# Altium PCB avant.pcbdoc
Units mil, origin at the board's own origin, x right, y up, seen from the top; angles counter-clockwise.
Board outline 360 x 525 mil, 2 copper layers (Top Layer, Bottom Layer), stack 62.2 mil thick; 5 components, 6 nets, 26 pads, 7 vias.
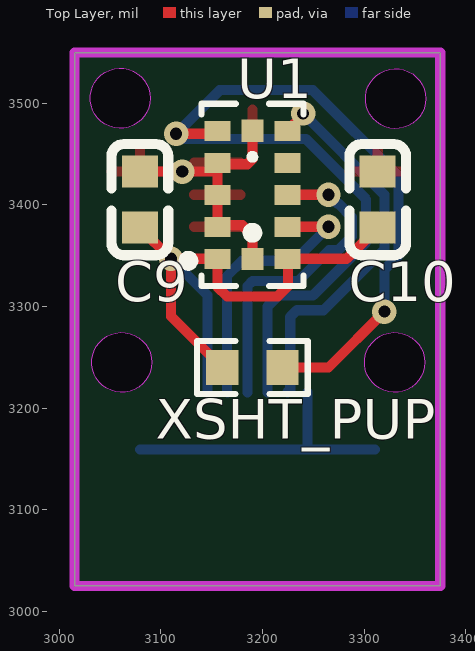
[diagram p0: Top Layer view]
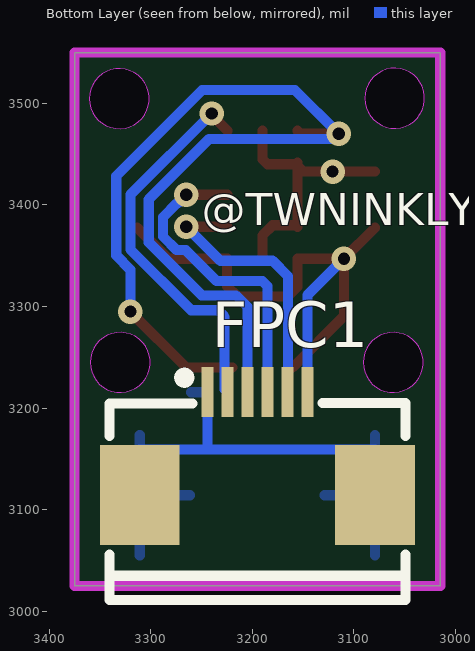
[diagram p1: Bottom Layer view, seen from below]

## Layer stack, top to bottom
Top Solder Mask Layer: solder mask 0.4, Dk 3.3
Top Layer: signal copper 1.4
Dielectric1: surface 59.4, FR4, Dk 4.5
Bottom Layer: signal copper 1.4
Bottom Solder Mask Layer: solder mask 0.4, Dk 3.3

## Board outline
3015,3550 3015,3025 3375,3025 3375,3550
cut-out: 3089.5,3505 3089.1,3500.3 3088,3495.6 3086.1,3491.3 3083.6,3487.3 3080.5,3483.7 3076.8,3480.7 3072.7,3478.3 3068.2,3476.6 3063.6,3475.7 3058.8,3475.5 3054.1,3476.1 3049.5,3477.4 3045.2,3479.4 3041.3,3482.1 3037.9,3485.4 3035,3489.2 3032.8,3493.4 3031.3,3497.9 3030.6,3502.6 3030.6,3507.4 3031.3,3512.1 3032.8,3516.6 3035,3520.8 3037.9,3524.6 3041.3,3527.9 3045.2,3530.6 3049.5,3532.6 3054.1,3533.9 3058.8,3534.5 3063.6,3534.3 3068.2,3533.4 3072.7,3531.7 3076.8,3529.3 3080.5,3526.3 3083.6,3522.7 3086.1,3518.7 3088,3514.4 3089.1,3509.7
cut-out: 3359.5,3245 3359.1,3240.3 3358,3235.6 3356.1,3231.3 3353.6,3227.3 3350.5,3223.7 3346.8,3220.7 3342.7,3218.3 3338.2,3216.6 3333.6,3215.7 3328.8,3215.5 3324.1,3216.1 3319.5,3217.4 3315.2,3219.4 3311.3,3222.1 3307.9,3225.4 3305,3229.2 3302.8,3233.4 3301.3,3237.9 3300.6,3242.6 3300.6,3247.4 3301.3,3252.1 3302.8,3256.6 3305,3260.8 3307.9,3264.6 3311.3,3267.9 3315.2,3270.6 3319.5,3272.6 3324.1,3273.9 3328.8,3274.5 3333.6,3274.3 3338.2,3273.4 3342.7,3271.7 3346.8,3269.3 3350.5,3266.3 3353.6,3262.7 3356.1,3258.7 3358,3254.4 3359.1,3249.7
cut-out: 3090.9,3245 3090.5,3240.3 3089.4,3235.6 3087.5,3231.3 3085,3227.3 3081.8,3223.7 3078.1,3220.7 3074,3218.3 3069.6,3216.6 3064.9,3215.7 3060.2,3215.5 3055.5,3216.1 3050.9,3217.4 3046.6,3219.4 3042.7,3222.1 3039.3,3225.4 3036.4,3229.2 3034.2,3233.4 3032.7,3237.9 3031.9,3242.6 3031.9,3247.4 3032.7,3252.1 3034.2,3256.6 3036.4,3260.8 3039.3,3264.6 3042.7,3267.9 3046.6,3270.6 3050.9,3272.6 3055.5,3273.9 3060.2,3274.5 3064.9,3274.3 3069.6,3273.4 3074,3271.7 3078.1,3269.3 3081.8,3266.3 3085,3262.7 3087.5,3258.7 3089.4,3254.4 3090.5,3249.7
cut-out: 3360.5,3504.6 3360.1,3499.9 3359,3495.3 3357.1,3490.9 3354.6,3486.9 3351.5,3483.3 3347.8,3480.3 3343.7,3477.9 3339.2,3476.3 3334.6,3475.3 3329.8,3475.1 3325.1,3475.7 3320.5,3477 3316.2,3479 3312.3,3481.7 3308.9,3485 3306,3488.8 3303.8,3493 3302.3,3497.5 3301.6,3502.2 3301.6,3507 3302.3,3511.7 3303.8,3516.2 3306,3520.4 3308.9,3524.2 3312.3,3527.5 3316.2,3530.2 3320.5,3532.2 3325.1,3533.5 3329.8,3534.1 3334.6,3533.9 3339.2,3533 3343.7,3531.3 3347.8,3528.9 3351.5,3525.9 3354.6,3522.4 3357.1,3518.3 3359,3514 3360.1,3509.4

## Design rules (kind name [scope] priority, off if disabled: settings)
BoardOutlineClearance copperThickness1oz [All] p0: genericclearance=10 ignorepadtopadclearanceinfootprint=FALSE except(0: Arc-SplitContinuation Track-SplitContinuation SMDPad-SplitContinuation THPad-SplitContinuation Via-SplitContinuation Fill-SplitContinuation Poly-SplitContinuation Region-SplitContinuation Text-SplitContinuation)
BoardOutlineClearance copperThickness2oz [All] p0: genericclearance=10 ignorepadtopadclearanceinfootprint=FALSE except(0: Arc-SplitContinuation Track-SplitContinuation SMDPad-SplitContinuation THPad-SplitContinuation Via-SplitContinuation Fill-SplitContinuation Poly-SplitContinuation Region-SplitContinuation Text-SplitContinuation)
BoardOutlineClearance Plane_innerPlane [All] p0: genericclearance=10 ignorepadtopadclearanceinfootprint=FALSE except(0: Arc-SplitContinuation Track-SplitContinuation SMDPad-SplitContinuation THPad-SplitContinuation Via-SplitContinuation Fill-SplitContinuation Poly-SplitContinuation Region-SplitContinuation Text-SplitContinuation)
BoardOutlineClearance Copper_copperRegion [All] p0: genericclearance=10 ignorepadtopadclearanceinfootprint=FALSE except(0: Arc-SplitContinuation Track-SplitContinuation SMDPad-SplitContinuation THPad-SplitContinuation Via-SplitContinuation Fill-SplitContinuation Poly-SplitContinuation Region-SplitContinuation Text-SplitContinuation)
BoardOutlineClearance otherClearance [All] p0: genericclearance=10 ignorepadtopadclearanceinfootprint=FALSE except(0: Arc-SplitContinuation Track-SplitContinuation SMDPad-SplitContinuation THPad-SplitContinuation Via-SplitContinuation Fill-SplitContinuation Poly-SplitContinuation Region-SplitContinuation Text-SplitContinuation)
Clearance copperThickness1oz [All] p1: gap=7 ignorepadtopadclearanceinfootprint=FALSE
Clearance copperThickness2oz [All] p1: gap=7 ignorepadtopadclearanceinfootprint=FALSE
Clearance Plane_innerPlane [All] p1: gap=7 ignorepadtopadclearanceinfootprint=FALSE
Clearance Copper_copperRegion [All] p1: gap=7 ignorepadtopadclearanceinfootprint=FALSE
Clearance otherClearance [All] p1: gap=7 ignorepadtopadclearanceinfootprint=FALSE
DiffPairsRouting differentialPair [All] p1: maxuncoupledlength=10 minlimit=6 maxlimit=Infinity mostfreqgap=6 toplayer_minwidth=5 toplayer_prefwidth=10 toplayer_maxwidth=100 bottomlayer_minwidth=5 bottomlayer_prefwidth=10 bottomlayer_maxwidth=100
PasteMaskExpansion pasteMaskExpansion [All] p1: expansion=0
PlaneConnect innerPlane [All] p1: planeconnectstyle=Relief reliefexpansion=20 reliefentries=4 reliefconductorwidth=10 reliefairgap=10
PolygonConnect copperRegion [All] p1: connectstyle=Relief reliefentries=4 reliefconductorwidth=10 polygonreliefangle="90 Angle" airgapwidth=10
RoutingVias viaSize [All] p1: viastyle="Through Hole" holewidth=12.0078 minholewidth=11.811 maxholewidth=248.0314 width=12.0078 minwidth=11.811 maxwidth=248.0314
SolderMaskExpansion solderMaskExpansion [IsVia] p1: useseparateexpansions=TRUE expansion=-1000 expansionbottom=-1000
SolderMaskExpansion solderMaskExpansion [All] p2: useseparateexpansions=TRUE expansion=2 expansionbottom=2
Width copperThickness1oz [All] p1: maxlimit=100 minlimit=5 preferedwidth=10
Width copperThickness2oz [All] p1: maxlimit=100 minlimit=8 preferedwidth=10

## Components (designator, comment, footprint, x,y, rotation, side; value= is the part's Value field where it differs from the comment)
C9 "100nF" C0603 3079.3,3405.2 r90 top
C10 "4.7uF" C0603 3313.4,3405.2 r90 top
FPC1 "FPC-05F-6PH20" FPC-SMD_6P-P0.50_XUNPU_FPC-05F-6PH20 3195,3165 r180 bottom
U1 "VL53L0CXV0DH/1" OPTO-SMD_12P_VL53L0CXV0DH-1 3190,3410 r270 top
XSHT_PUP "10kΩ" R0603 3190,3240 r180 top

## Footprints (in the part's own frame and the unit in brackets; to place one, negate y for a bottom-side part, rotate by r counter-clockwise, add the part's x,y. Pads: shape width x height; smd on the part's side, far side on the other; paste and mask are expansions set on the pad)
C0603 [mil]
  rect 31.5x35.4 smd: 1(-27.6,0) 2(27.6,0)
  silkscreen extent -55,-28 55,28
FPC-SMD_6P-P0.50_XUNPU_FPC-05F-6PH20 [mil]
  rect 11.8x49.2 smd paste+0 mask+2: 1(-49.2,50.7) 2(-29.5,50.7) 3(-9.8,50.7) 4(9.8,50.7) 5(29.5,50.7) 6(49.2,50.7)
  rect 78.7x98.4 smd paste+0 mask+2: 7(115.7,-50.7) 8(-115.8,-50.7)
  silkscreen extent -146,-154 146,70
OPTO-SMD_12P_VL53L0CXV0DH-1 [mil]
  rect 19.7x25.6 smd: 1(63,-34.4) 2(31.5,-34.4) 3(0,-34.4) 4(-31.5,-34.4) 5(-63,-34.4) 7(-63,34.4) 8(-31.5,34.4) 9(0,34.4) 10(31.5,34.4) 11(63,34.4)
  rect 21.7x21.7 smd: 6(-63,0) 12(63,0)
  silkscreen extent -90,-68 90,50
R0603 [mil]
  rect 31.8x34 smd paste-3937 mask+2: 1(-29.7,0) 2(29.7,0)
  silkscreen extent -54,-26 54,26

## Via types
v1: diameter 24, hole 12, Top Layer to Bottom Layer, 7 vias

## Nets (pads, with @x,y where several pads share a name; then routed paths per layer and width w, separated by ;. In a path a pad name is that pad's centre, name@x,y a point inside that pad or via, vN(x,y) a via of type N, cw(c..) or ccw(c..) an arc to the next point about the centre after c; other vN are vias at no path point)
3V3: C9.1 C10.1 FPC1.6 U1.1 U1.11 XSHT_PUP.2 | length 597
  Top Layer w10: C9.1 v1(3109.9,3347) ; XSHT_PUP.2 3109.9,3290.4 v1(3109.9,3347) ; C10.1 3282.8,3347 U1.11 3225,3346.5 3225,3320 3215,3310 3165,3310 3155.6,3319.4 U1.1 v1(3109.9,3347)
  Bottom Layer w10: v1(3109.9,3347) 3145.8,3311.1 FPC1.6
GND: C9.2 C10.2 FPC1.1 FPC1.7 FPC1.8 U1.2 U1.3 U1.4 U1.6 U1.12 | length 559
  Top Layer w10: C9.2 v1(3121,3432.8) 3149.8,3432.8 U1.4@3155.6,3438.5 ; U1.2 U1.2@3157.1,3380 ; U1.12 3190,3370 3180,3380 U1.2@3157.1,3380 ; U1.6 3190,3445 3185,3440 U1.4@3157.1,3440 ; U1.4@3155.6,3438.5 U1.4@3157.1,3440 ; U1.4@3155.6,3438.5 U1.3 3155.6,3381.5 U1.2@3157.1,3380 ; U1.4@3155.6,3438.5 U1.4 U1.4@3157.1,3440
  Bottom Layer w10: FPC1.7@3079.3,3159.3 3241.9,3159.3 ; FPC1.1 3244.2,3161.6 3241.9,3159.3 ; FPC1.8@3310.8,3159.3 3241.9,3159.3
GP1: FPC1.2 U1.7 | length 385.9
  Top Layer w10: U1.7 3240,3488.5 v1(3240,3490)
  Bottom Layer w10: FPC1.2 3227.3,3218.5 3227.3,3289.8 3233.8,3296.3 3260.1,3296.3 3320,3356.2 3320,3410 v1(3240,3490)
SCL: FPC1.5 U1.10 | length 275.2
  Top Layer w10: U1.10 v1(3265,3378.5)
  Bottom Layer w10: FPC1.5 3165,3216.2 3165,3330 3180,3345 3231.5,3345 v1(3265,3378.5)
SDA: FPC1.4 U1.9 | length 319.2
  Top Layer w10: U1.9 v1(3265,3410)
  Bottom Layer w10: FPC1.4 3185.2,3320.2 3190,3325 3235,3325 3265.5,3355.5 3274.5,3355.5 3288,3369 3288,3388 3274.5,3401.5 3273.5,3401.5 v1(3265,3410)
XSHUT: FPC1.3 U1.5 XSHT_PUP.1 | length 1039.6
  Top Layer w10: v1(3115,3470) 3152.6,3470 U1.5 ; XSHT_PUP.1 3265,3240 v1(3320,3295)
  Bottom Layer w10: FPC1.3 3204.8,3299.8 3216,3311 3249.8,3311 3302,3363.2 3302,3405.5 3242.5,3465 3120,3465 v1(3115,3470) 3158,3513 3249.5,3513 3334,3428.5 3334,3350.4 3320,3336.3 v1(3320,3295)
pads on no net: U1.8

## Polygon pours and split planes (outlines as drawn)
GND on Top Layer (solid, remove dead copper, pour order 0): 3000,3565 3000,3005 3385,3005 3385,3565
GND on Bottom Layer (solid, remove dead copper, pour order 2): 3000,3570 3000,3000 3390,3000 3390,3570

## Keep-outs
Board Outline Layer:
  region: 3089.5,3505 3089.1,3500.3 3088,3495.6 3086.1,3491.3 3083.6,3487.3 3080.5,3483.7 3076.8,3480.7 3072.7,3478.3 3068.2,3476.6 3063.6,3475.7 3058.8,3475.5 3054.1,3476.1 3049.5,3477.4 3045.2,3479.4 3041.3,3482.1 3037.9,3485.4 3035,3489.2 3032.8,3493.4 3031.3,3497.9 3030.6,3502.6 3030.6,3507.4 3031.3,3512.1 3032.8,3516.6 3035,3520.8 3037.9,3524.6 3041.3,3527.9 3045.2,3530.6 3049.5,3532.6 3054.1,3533.9 3058.8,3534.5 3063.6,3534.3 3068.2,3533.4 3072.7,3531.7 3076.8,3529.3 3080.5,3526.3 3083.6,3522.7 3086.1,3518.7 3088,3514.4 3089.1,3509.7
  region: 3089.5,3505 3089.1,3500.3 3088,3495.6 3086.1,3491.3 3083.6,3487.3 3080.5,3483.7 3076.8,3480.7 3072.7,3478.3 3068.2,3476.6 3063.6,3475.7 3058.8,3475.5 3054.1,3476.1 3049.5,3477.4 3045.2,3479.4 3041.3,3482.1 3037.9,3485.4 3035,3489.2 3032.8,3493.4 3031.3,3497.9 3030.6,3502.6 3030.6,3507.4 3031.3,3512.1 3032.8,3516.6 3035,3520.8 3037.9,3524.6 3041.3,3527.9 3045.2,3530.6 3049.5,3532.6 3054.1,3533.9 3058.8,3534.5 3063.6,3534.3 3068.2,3533.4 3072.7,3531.7 3076.8,3529.3 3080.5,3526.3 3083.6,3522.7 3086.1,3518.7 3088,3514.4 3089.1,3509.7
  region: 3359.5,3245 3359.1,3240.3 3358,3235.6 3356.1,3231.3 3353.6,3227.3 3350.5,3223.7 3346.8,3220.7 3342.7,3218.3 3338.2,3216.6 3333.6,3215.7 3328.8,3215.5 3324.1,3216.1 3319.5,3217.4 3315.2,3219.4 3311.3,3222.1 3307.9,3225.4 3305,3229.2 3302.8,3233.4 3301.3,3237.9 3300.6,3242.6 3300.6,3247.4 3301.3,3252.1 3302.8,3256.6 3305,3260.8 3307.9,3264.6 3311.3,3267.9 3315.2,3270.6 3319.5,3272.6 3324.1,3273.9 3328.8,3274.5 3333.6,3274.3 3338.2,3273.4 3342.7,3271.7 3346.8,3269.3 3350.5,3266.3 3353.6,3262.7 3356.1,3258.7 3358,3254.4 3359.1,3249.7
  region: 3359.5,3245 3359.1,3240.3 3358,3235.6 3356.1,3231.3 3353.6,3227.3 3350.5,3223.7 3346.8,3220.7 3342.7,3218.3 3338.2,3216.6 3333.6,3215.7 3328.8,3215.5 3324.1,3216.1 3319.5,3217.4 3315.2,3219.4 3311.3,3222.1 3307.9,3225.4 3305,3229.2 3302.8,3233.4 3301.3,3237.9 3300.6,3242.6 3300.6,3247.4 3301.3,3252.1 3302.8,3256.6 3305,3260.8 3307.9,3264.6 3311.3,3267.9 3315.2,3270.6 3319.5,3272.6 3324.1,3273.9 3328.8,3274.5 3333.6,3274.3 3338.2,3273.4 3342.7,3271.7 3346.8,3269.3 3350.5,3266.3 3353.6,3262.7 3356.1,3258.7 3358,3254.4 3359.1,3249.7
  region: 3090.9,3245 3090.5,3240.3 3089.4,3235.6 3087.5,3231.3 3085,3227.3 3081.8,3223.7 3078.1,3220.7 3074,3218.3 3069.6,3216.6 3064.9,3215.7 3060.2,3215.5 3055.5,3216.1 3050.9,3217.4 3046.6,3219.4 3042.7,3222.1 3039.3,3225.4 3036.4,3229.2 3034.2,3233.4 3032.7,3237.9 3031.9,3242.6 3031.9,3247.4 3032.7,3252.1 3034.2,3256.6 3036.4,3260.8 3039.3,3264.6 3042.7,3267.9 3046.6,3270.6 3050.9,3272.6 3055.5,3273.9 3060.2,3274.5 3064.9,3274.3 3069.6,3273.4 3074,3271.7 3078.1,3269.3 3081.8,3266.3 3085,3262.7 3087.5,3258.7 3089.4,3254.4 3090.5,3249.7
  region: 3090.9,3245 3090.5,3240.3 3089.4,3235.6 3087.5,3231.3 3085,3227.3 3081.8,3223.7 3078.1,3220.7 3074,3218.3 3069.6,3216.6 3064.9,3215.7 3060.2,3215.5 3055.5,3216.1 3050.9,3217.4 3046.6,3219.4 3042.7,3222.1 3039.3,3225.4 3036.4,3229.2 3034.2,3233.4 3032.7,3237.9 3031.9,3242.6 3031.9,3247.4 3032.7,3252.1 3034.2,3256.6 3036.4,3260.8 3039.3,3264.6 3042.7,3267.9 3046.6,3270.6 3050.9,3272.6 3055.5,3273.9 3060.2,3274.5 3064.9,3274.3 3069.6,3273.4 3074,3271.7 3078.1,3269.3 3081.8,3266.3 3085,3262.7 3087.5,3258.7 3089.4,3254.4 3090.5,3249.7
  region: 3360.5,3504.6 3360.1,3499.9 3359,3495.3 3357.1,3490.9 3354.6,3486.9 3351.5,3483.3 3347.8,3480.3 3343.7,3477.9 3339.2,3476.3 3334.6,3475.3 3329.8,3475.1 3325.1,3475.7 3320.5,3477 3316.2,3479 3312.3,3481.7 3308.9,3485 3306,3488.8 3303.8,3493 3302.3,3497.5 3301.6,3502.2 3301.6,3507 3302.3,3511.7 3303.8,3516.2 3306,3520.4 3308.9,3524.2 3312.3,3527.5 3316.2,3530.2 3320.5,3532.2 3325.1,3533.5 3329.8,3534.1 3334.6,3533.9 3339.2,3533 3343.7,3531.3 3347.8,3528.9 3351.5,3525.9 3354.6,3522.4 3357.1,3518.3 3359,3514 3360.1,3509.4
  region: 3360.5,3504.6 3360.1,3499.9 3359,3495.3 3357.1,3490.9 3354.6,3486.9 3351.5,3483.3 3347.8,3480.3 3343.7,3477.9 3339.2,3476.3 3334.6,3475.3 3329.8,3475.1 3325.1,3475.7 3320.5,3477 3316.2,3479 3312.3,3481.7 3308.9,3485 3306,3488.8 3303.8,3493 3302.3,3497.5 3301.6,3502.2 3301.6,3507 3302.3,3511.7 3303.8,3516.2 3306,3520.4 3308.9,3524.2 3312.3,3527.5 3316.2,3530.2 3320.5,3532.2 3325.1,3533.5 3329.8,3534.1 3334.6,3533.9 3339.2,3533 3343.7,3531.3 3347.8,3528.9 3351.5,3525.9 3354.6,3522.4 3357.1,3518.3 3359,3514 3360.1,3509.4
  lines w0.1: 3030.6,3502.6 3031.3,3497.9 3032.8,3493.4 3035,3489.2 3037.9,3485.4 3041.3,3482.1 3045.2,3479.4 3049.5,3477.4 3054.1,3476.1 3058.8,3475.5 3063.6,3475.7 3068.2,3476.6 3072.7,3478.3 3076.8,3480.7 3080.5,3483.7 3083.6,3487.3 3086.1,3491.3 3088,3495.6 3089.1,3500.3 3089.5,3505 3089.1,3509.7 3088,3514.4 3086.1,3518.7 3083.6,3522.7 3080.5,3526.3 3076.8,3529.3 3072.7,3531.7 3068.2,3533.4 3063.6,3534.3 3058.8,3534.5 3054.1,3533.9 3049.5,3532.6 3045.2,3530.6 3041.3,3527.9 3037.9,3524.6 3035,3520.8 3032.8,3516.6 3031.3,3512.1 3030.6,3507.4 3030.6,3502.6 ; 3031.9,3242.6 3032.7,3237.9 3034.2,3233.4 3036.4,3229.2 3039.3,3225.4 3042.7,3222.1 3046.6,3219.4 3050.9,3217.4 3055.5,3216.1 3060.2,3215.5 3064.9,3215.7 3069.6,3216.6 3074,3218.3 3078.1,3220.7 3081.8,3223.7 3085,3227.3 3087.5,3231.3 3089.4,3235.6 3090.5,3240.3 3090.9,3245 3090.5,3249.7 3089.4,3254.4 3087.5,3258.7 3085,3262.7 3081.8,3266.3 3078.1,3269.3 3074,3271.7 3069.6,3273.4 3064.9,3274.3 3060.2,3274.5 3055.5,3273.9 3050.9,3272.6 3046.6,3270.6 3042.7,3267.9 3039.3,3264.6 3036.4,3260.8 3034.2,3256.6 3032.7,3252.1 3031.9,3247.4 3031.9,3242.6 ; 3300.6,3242.6 3301.3,3237.9 3302.8,3233.4 3305,3229.2 3307.9,3225.4 3311.3,3222.1 3315.2,3219.4 3319.5,3217.4 3324.1,3216.1 3328.8,3215.5 3333.6,3215.7 3338.2,3216.6 3342.7,3218.3 3346.8,3220.7 3350.5,3223.7 3353.6,3227.3 3356.1,3231.3 3358,3235.6 3359.1,3240.3 3359.5,3245 3359.1,3249.7 3358,3254.4 3356.1,3258.7 3353.6,3262.7 3350.5,3266.3 3346.8,3269.3 3342.7,3271.7 3338.2,3273.4 3333.6,3274.3 3328.8,3274.5 3324.1,3273.9 3319.5,3272.6 3315.2,3270.6 3311.3,3267.9 3307.9,3264.6 3305,3260.8 3302.8,3256.6 3301.3,3252.1 3300.6,3247.4 3300.6,3242.6 ; 3301.6,3502.2 3302.3,3497.5 3303.8,3493 3306,3488.8 3308.9,3485 3312.3,3481.7 3316.2,3479 3320.5,3477 3325.1,3475.7 3329.8,3475.1 3334.6,3475.3 3339.2,3476.3 3343.7,3477.9 3347.8,3480.3 3351.5,3483.3 3354.6,3486.9 3357.1,3490.9 3359,3495.3 3360.1,3499.9 3360.5,3504.6 3360.1,3509.4 3359,3514 3357.1,3518.3 3354.6,3522.4 3351.5,3525.9 3347.8,3528.9 3343.7,3531.3 3339.2,3533 3334.6,3533.9 3329.8,3534.1 3325.1,3533.5 3320.5,3532.2 3316.2,3530.2 3312.3,3527.5 3308.9,3524.2 3306,3520.4 3303.8,3516.2 3302.3,3511.7 3301.6,3507 3301.6,3502.2
  lines w10: 3015,3025 3015,3550 3375,3550 3375,3025 3015,3025

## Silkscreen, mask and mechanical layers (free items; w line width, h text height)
Bottom Silkscreen Layer:
  text "@TWNINKLY09" at 3250,3380 h31.5
Mechanical Layer:
  drawing of 156 lines, arcs and shapes, not listed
